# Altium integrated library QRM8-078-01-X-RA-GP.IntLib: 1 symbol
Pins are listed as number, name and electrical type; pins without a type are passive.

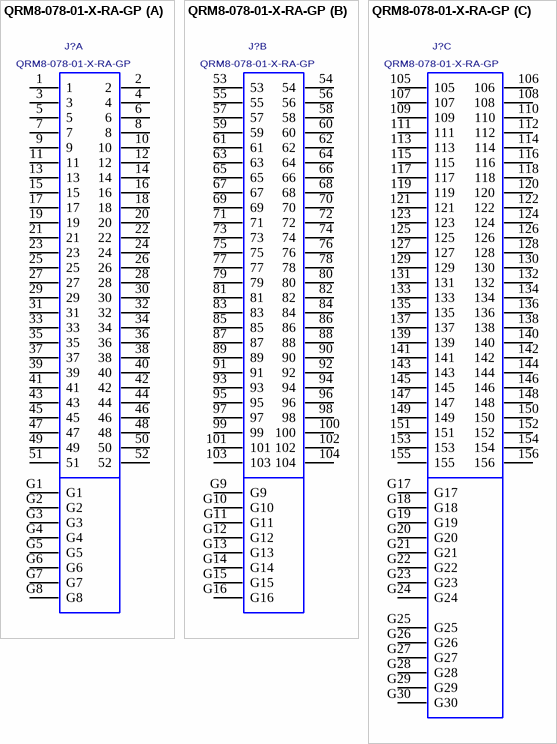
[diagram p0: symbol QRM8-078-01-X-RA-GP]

## QRM8-078-01-X-RA-GP
designator J?
.8mm Q-Rate  Right Angle Terminal  Assembly.; MANUFACTURER: SAMTEC
footprint QRM8-078-01-X-RA-GP
part A pins: 1, 2, 3, 4, 5, 6, 7, 8, 9, 10, 11, 12, 13, 14, 15, 16, 17, 18, 19, 20, 21, 22, 23, 24, 25, 26, 27, 28, 29, 30, 31, 32, 33, 34, 35, 36, 37, 38, 39, 40, 41, 42, 43, 44, 45, 46, 47, 48, 49, 50, 51, 52, G1, G2, G3, G4, G5, G6, G7, G8
part B pins: 53, 54, 55, 56, 57, 58, 59, 60, 61, 62, 63, 64, 65, 66, 67, 68, 69, 70, 71, 72, 73, 74, 75, 76, 77, 78, 79, 80, 81, 82, 83, 84, 85, 86, 87, 88, 89, 90, 91, 92, 93, 94, 95, 96, 97, 98, 99, 100, 101, 102, 103, 104, G9, G10, G11, G12, G13, G14, G15, G16
part C pins: 105, 106, 107, 108, 109, 110, 111, 112, 113, 114, 115, 116, 117, 118, 119, 120, 121, 122, 123, 124, 125, 126, 127, 128, 129, 130, 131, 132, 133, 134, 135, 136, 137, 138, 139, 140, 141, 142, 143, 144, 145, 146, 147, 148, 149, 150, 151, 152, 153, 154, 155, 156, G17, G18, G19, G20, G21, G22, G23, G24, G25, G26, G27, G28, G29, G30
